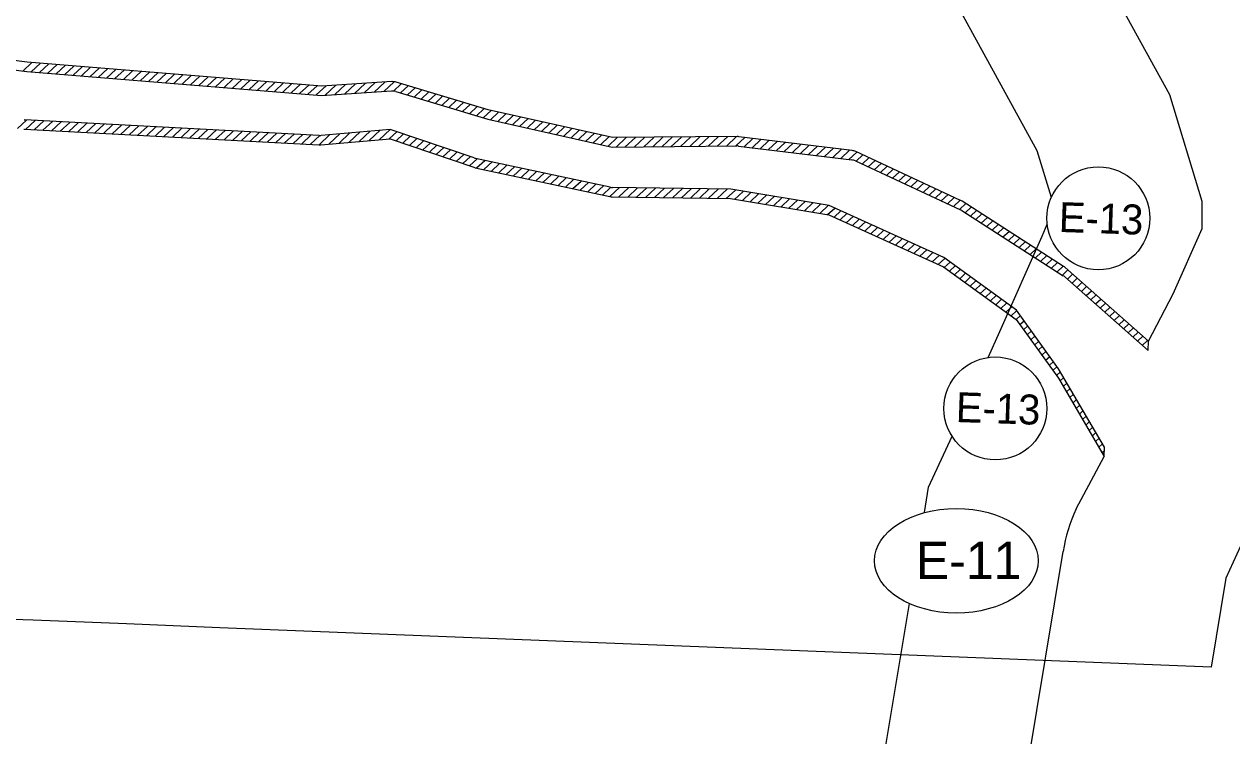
# Model space of a CAD drawing. Extents: x 977239 to 983725, y 1525948 to 1526901.
# Drawn here: x 977835.8 to 978029.8, y 1526495.3 to 1526609.6 of the extents above; entities that cross this region are included whole.
import ezdxf

# ---------------------------------------------------------------- set-up
doc = ezdxf.new("R2010")
doc.units = 0
for name, color, linetype in [('R_Erosion', 7, 'Continuous'), ('R_No Plot', 7, 'Continuous'), ('R_Water', 7, 'Continuous')]:
    doc.layers.add(name, color=color, linetype=linetype)

msp = doc.modelspace()

# ---------------------------------------------------------------- linework, layer by layer
at = {"layer": 'R_Erosion'}
for p, q in [((977835.63, 1526602.04), (977837.08, 1526603.4)), ((977836.95, 1526601.91), (977838.43, 1526603.29)), ((977838.3, 1526601.8), (977839.78, 1526603.18)), ((977839.65, 1526601.69), (977841.13, 1526603.07)), ((977840.99, 1526601.58), (977842.47, 1526602.96)), ((977842.34, 1526601.47), (977843.82, 1526602.85)), ((977843.69, 1526601.36), (977845.17, 1526602.74)), ((977845.04, 1526601.25), (977846.51, 1526602.64)), ((977846.38, 1526601.14), (977847.86, 1526602.53)), ((977847.73, 1526601.03), (977849.21, 1526602.42)), ((977849.08, 1526600.92), (977850.56, 1526602.31)), ((977850.42, 1526600.82), (977851.9, 1526602.2)), ((977851.77, 1526600.71), (977853.25, 1526602.09)), ((977853.12, 1526600.6), (977854.6, 1526601.98)), ((977854.47, 1526600.49), (977855.95, 1526601.87)), ((977855.81, 1526600.38), (977857.29, 1526601.76)), ((977857.16, 1526600.27), (977858.64, 1526601.65)), ((977858.51, 1526600.16), (977859.99, 1526601.55)), ((977859.86, 1526600.05), (977861.33, 1526601.44)), ((977861.2, 1526599.94), (977862.68, 1526601.33)), ((977862.55, 1526599.84), (977864.03, 1526601.22)), ((977863.9, 1526599.73), (977865.38, 1526601.11)), ((977865.25, 1526599.62), (977866.72, 1526601)), ((977866.59, 1526599.51), (977868.07, 1526600.89)), ((977867.94, 1526599.4), (977869.42, 1526600.78)), ((977869.29, 1526599.29), (977870.77, 1526600.67)), ((977870.63, 1526599.18), (977872.11, 1526600.56)), ((977871.98, 1526599.07), (977873.46, 1526600.46)), ((977873.33, 1526598.96), (977874.81, 1526600.35)), ((977874.68, 1526598.85), (977876.16, 1526600.24)), ((977876.02, 1526598.75), (977877.5, 1526600.13)), ((977877.37, 1526598.64), (977878.85, 1526600.02)), ((977878.72, 1526598.53), (977880.2, 1526599.91)), ((977880.07, 1526598.42), (977881.54, 1526599.8)), ((977881.41, 1526598.31), (977882.89, 1526599.69)), ((977882.76, 1526598.2), (977884.33, 1526599.67)), ((977884.19, 1526598.17), (977885.9, 1526599.77)), ((977885.76, 1526598.27), (977887.47, 1526599.87)), ((977887.33, 1526598.36), (977889.04, 1526599.97)), ((977888.9, 1526598.46), (977890.61, 1526600.07)), ((977890.47, 1526598.56), (977892.18, 1526600.17)), ((977892.04, 1526598.66), (977893.75, 1526600.26)), ((977893.6, 1526598.76), (977895.27, 1526600.32)), ((977895.14, 1526598.83), (977896.4, 1526600.01)), ((977896.28, 1526598.53), (977897.51, 1526599.67)), ((977897.39, 1526598.2), (977898.62, 1526599.34)), ((977898.5, 1526597.86), (977899.73, 1526599.01)), ((977899.61, 1526597.53), (977900.83, 1526598.68)), ((977900.72, 1526597.2), (977901.94, 1526598.34)), ((977901.83, 1526596.86), (977903.05, 1526598.01)), ((977902.93, 1526596.53), (977904.16, 1526597.68)), ((977904.04, 1526596.2), (977905.27, 1526597.35)), ((977905.15, 1526595.87), (977906.38, 1526597.01)), ((977906.26, 1526595.53), (977907.48, 1526596.68)), ((977907.37, 1526595.2), (977908.59, 1526596.35)), ((977908.47, 1526594.87), (977909.7, 1526596.01)), ((977909.58, 1526594.54), (977910.84, 1526595.71)), ((977910.72, 1526594.23), (977912.02, 1526595.45)), ((977911.9, 1526593.96), (977913.2, 1526595.18)), ((977834.74, 1526592.8), (977836.21, 1526594.17)), ((977883.24, 1526591.72), (977835.93, 1526594.19)), ((977883.24, 1526591.72), (977835.93, 1526594.19)), ((977883.24, 1526591.72), (977835.93, 1526594.19)), ((977836.07, 1526592.68), (977837.59, 1526594.1)), ((977837.46, 1526592.61), (977838.98, 1526594.03)), ((977838.85, 1526592.53), (977840.37, 1526593.96)), ((977840.23, 1526592.46), (977841.75, 1526593.88)), ((977841.62, 1526592.39), (977843.14, 1526593.81)), ((977843.01, 1526592.32), (977844.53, 1526593.74)), ((977844.39, 1526592.24), (977845.91, 1526593.67)), ((977845.78, 1526592.17), (977847.3, 1526593.59)), ((977847.16, 1526592.1), (977848.69, 1526593.52)), ((977848.55, 1526592.03), (977850.07, 1526593.45)), ((977849.94, 1526591.95), (977851.46, 1526593.38)), ((977851.32, 1526591.88), (977852.84, 1526593.3)), ((977852.71, 1526591.81), (977854.23, 1526593.23)), ((977854.1, 1526591.74), (977855.62, 1526593.16)), ((977913.08, 1526593.7), (977914.38, 1526594.92)), ((977914.26, 1526593.43), (977915.56, 1526594.65)), ((977915.44, 1526593.17), (977916.74, 1526594.39)), ((977916.62, 1526592.9), (977917.93, 1526594.12)), ((977917.8, 1526592.64), (977919.11, 1526593.86)), ((977918.99, 1526592.38), (977920.29, 1526593.6)), ((977920.17, 1526592.11), (977921.47, 1526593.33)), ((977835.88, 1526592.69), (977883.19, 1526590.22)), ((977835.88, 1526592.69), (977883.19, 1526590.22)), ((977855.48, 1526591.66), (977857, 1526593.09)), ((977856.87, 1526591.59), (977858.39, 1526593.01)), ((977858.26, 1526591.52), (977859.78, 1526592.94)), ((977859.64, 1526591.45), (977861.16, 1526592.87)), ((977861.03, 1526591.37), (977862.55, 1526592.8)), ((977862.42, 1526591.3), (977863.94, 1526592.72)), ((977863.8, 1526591.23), (977865.32, 1526592.65)), ((977865.19, 1526591.16), (977866.71, 1526592.58)), ((977866.57, 1526591.09), (977868.1, 1526592.51)), ((977867.96, 1526591.01), (977869.48, 1526592.44)), ((977869.35, 1526590.94), (977870.87, 1526592.36)), ((977870.73, 1526590.87), (977872.25, 1526592.29)), ((977872.12, 1526590.8), (977873.64, 1526592.22)), ((977873.51, 1526590.72), (977875.03, 1526592.15)), ((977874.89, 1526590.65), (977876.41, 1526592.07)), ((977876.28, 1526590.58), (977877.8, 1526592)), ((977877.67, 1526590.51), (977879.19, 1526591.93)), ((977879.05, 1526590.43), (977880.57, 1526591.86)), ((977880.44, 1526590.36), (977881.96, 1526591.78)), ((977881.83, 1526590.29), (977883.35, 1526591.71)), ((977883.21, 1526590.22), (977884.95, 1526591.84)), ((977884.8, 1526590.34), (977886.56, 1526591.98)), ((977886.41, 1526590.47), (977888.17, 1526592.12)), ((977888.03, 1526590.61), (977889.78, 1526592.26)), ((977889.64, 1526590.75), (977891.4, 1526592.39)), ((977891.25, 1526590.89), (977893.01, 1526592.53)), ((977892.86, 1526591.02), (977894.62, 1526592.67)), ((977894.47, 1526591.16), (977895.7, 1526592.31)), ((977895.59, 1526590.84), (977896.77, 1526591.95)), ((977896.66, 1526590.47), (977897.85, 1526591.58)), ((977897.73, 1526590.11), (977898.92, 1526591.22)), ((977921.35, 1526591.85), (977922.65, 1526593.07)), ((977922.53, 1526591.58), (977923.83, 1526592.8)), ((977923.71, 1526591.32), (977925.01, 1526592.54)), ((977924.89, 1526591.05), (977926.19, 1526592.27)), ((977926.07, 1526590.79), (977927.38, 1526592.01)), ((977927.25, 1526590.53), (977928.56, 1526591.75)), ((977928.44, 1526590.26), (977929.74, 1526591.48)), ((977929.62, 1526590), (977931.07, 1526591.35)), ((977930.93, 1526589.85), (977932.54, 1526591.37)), ((977932.4, 1526589.87), (977934.02, 1526591.38)), ((977933.88, 1526589.88), (977935.5, 1526591.39)), ((977935.36, 1526589.89), (977936.98, 1526591.4)), ((977936.84, 1526589.9), (977938.45, 1526591.42)), ((977938.31, 1526589.92), (977939.93, 1526591.43)), ((977939.79, 1526589.93), (977941.41, 1526591.44)), ((977941.27, 1526589.94), (977942.88, 1526591.45)), ((977942.74, 1526589.95), (977944.36, 1526591.47)), ((977944.22, 1526589.97), (977945.84, 1526591.48)), ((977945.7, 1526589.98), (977947.32, 1526591.49)), ((977947.18, 1526589.99), (977948.79, 1526591.5)), ((977948.65, 1526590), (977950.27, 1526591.52)), ((977950.13, 1526590.02), (977951.59, 1526591.39)), ((977968.82, 1526589.29), (977950.64, 1526591.5)), ((977968.82, 1526589.29), (977950.64, 1526591.5)), ((977951.47, 1526589.9), (977952.89, 1526591.23)), ((977898.81, 1526589.74), (977899.99, 1526590.85)), ((977899.88, 1526589.38), (977901.07, 1526590.49)), ((977900.95, 1526589.01), (977902.14, 1526590.12)), ((977902.03, 1526588.65), (977903.22, 1526589.76)), ((977903.1, 1526588.28), (977904.29, 1526589.39)), ((977950.59, 1526590), (977968.77, 1526587.79)), ((977952.76, 1526589.74), (977954.18, 1526591.07)), ((977954.06, 1526589.58), (977955.48, 1526590.91)), ((977955.35, 1526589.42), (977956.77, 1526590.75)), ((977956.65, 1526589.26), (977958.07, 1526590.6)), ((977957.94, 1526589.11), (977959.36, 1526590.44)), ((977959.24, 1526588.95), (977960.66, 1526590.28)), ((977960.53, 1526588.79), (977961.95, 1526590.12)), ((977961.83, 1526588.63), (977963.25, 1526589.96)), ((977963.12, 1526588.48), (977964.54, 1526589.81)), ((977964.42, 1526588.32), (977965.84, 1526589.65)), ((977965.71, 1526588.16), (977967.13, 1526589.49)), ((977967.01, 1526588), (977968.43, 1526589.33)), ((977904.17, 1526587.92), (977905.36, 1526589.03)), ((977905.25, 1526587.55), (977906.44, 1526588.66)), ((977906.32, 1526587.19), (977907.51, 1526588.3)), ((977907.39, 1526586.82), (977908.62, 1526587.97)), ((977929.96, 1526583.39), (977908.34, 1526588.03)), ((977929.96, 1526583.39), (977908.34, 1526588.03)), ((977929.96, 1526583.39), (977908.34, 1526588.03)), ((977908.5, 1526586.49), (977909.81, 1526587.71)), ((977909.69, 1526586.23), (977911, 1526587.46)), ((977968.3, 1526587.84), (977969.58, 1526589.04)), ((977969.37, 1526587.61), (977986.22, 1526579.77)), ((977986.27, 1526581.27), (977969.42, 1526589.11)), ((977986.27, 1526581.27), (977969.42, 1526589.11)), ((977969.47, 1526587.57), (977970.56, 1526588.59)), ((977970.45, 1526587.11), (977971.53, 1526588.13)), ((977971.43, 1526586.66), (977972.51, 1526587.68)), ((977908.29, 1526586.53), (977929.91, 1526581.89)), ((977908.29, 1526586.53), (977929.91, 1526581.89)), ((977910.88, 1526585.98), (977912.19, 1526587.2)), ((977912.07, 1526585.72), (977913.39, 1526586.95)), ((977913.26, 1526585.46), (977914.58, 1526586.69)), ((977914.45, 1526585.21), (977915.77, 1526586.44)), ((977915.65, 1526584.95), (977916.96, 1526586.18)), ((977916.84, 1526584.7), (977918.15, 1526585.93)), ((977918.03, 1526584.44), (977919.34, 1526585.67)), ((977919.22, 1526584.19), (977920.53, 1526585.42)), ((977972.4, 1526586.2), (977973.49, 1526587.22)), ((977973.38, 1526585.75), (977974.47, 1526586.77)), ((977974.36, 1526585.29), (977975.44, 1526586.31)), ((977975.33, 1526584.84), (977976.42, 1526585.85)), ((977976.31, 1526584.38), (977977.4, 1526585.4)), ((977920.41, 1526583.93), (977921.72, 1526585.16)), ((977921.6, 1526583.68), (977922.91, 1526584.91)), ((977922.79, 1526583.42), (977924.1, 1526584.65)), ((977923.98, 1526583.17), (977925.29, 1526584.39)), ((977925.17, 1526582.91), (977926.48, 1526584.14)), ((977926.36, 1526582.66), (977927.68, 1526583.88)), ((977927.55, 1526582.4), (977928.87, 1526583.63)), ((977977.29, 1526583.93), (977978.38, 1526584.94)), ((977978.27, 1526583.47), (977979.35, 1526584.49)), ((977979.24, 1526583.02), (977980.33, 1526584.03)), ((977980.22, 1526582.56), (977981.31, 1526583.58)), ((977928.74, 1526582.14), (977930.06, 1526583.38)), ((977929.93, 1526581.89), (977931.48, 1526583.33)), ((977931.34, 1526581.83), (977932.92, 1526583.31)), ((977932.78, 1526581.81), (977934.36, 1526583.29)), ((977934.22, 1526581.79), (977935.8, 1526583.27)), ((977935.66, 1526581.77), (977937.24, 1526583.24)), ((977937.1, 1526581.75), (977938.68, 1526583.22)), ((977938.54, 1526581.72), (977940.12, 1526583.2)), ((977939.98, 1526581.7), (977941.56, 1526583.18)), ((977941.42, 1526581.68), (977943, 1526583.16)), ((977942.86, 1526581.66), (977944.44, 1526583.14)), ((977944.3, 1526581.64), (977945.88, 1526583.11)), ((977945.74, 1526581.62), (977947.32, 1526583.09)), ((977947.18, 1526581.59), (977948.76, 1526583.07)), ((977948.62, 1526581.57), (977950.09, 1526582.94)), ((977949.96, 1526581.45), (977951.33, 1526582.73)), ((977951.21, 1526581.25), (977952.58, 1526582.53)), ((977952.45, 1526581.04), (977953.82, 1526582.33)), ((977953.7, 1526580.84), (977955.07, 1526582.12)), ((977954.94, 1526580.63), (977956.31, 1526581.92)), ((977956.19, 1526580.43), (977957.56, 1526581.71)), ((977957.43, 1526580.23), (977958.8, 1526581.51)), ((977981.2, 1526582.11), (977982.29, 1526583.12)), ((977982.18, 1526581.65), (977983.26, 1526582.67)), ((977983.15, 1526581.2), (977984.24, 1526582.21)), ((977984.13, 1526580.74), (977985.22, 1526581.76)), ((977958.68, 1526580.02), (977960.05, 1526581.3)), ((977959.92, 1526579.82), (977961.29, 1526581.1)), ((977961.17, 1526579.61), (977962.54, 1526580.89)), ((977962.41, 1526579.41), (977963.78, 1526580.69)), ((977963.66, 1526579.2), (977965.03, 1526580.49)), ((977964.9, 1526579), (977966.04, 1526580.06)), ((977965.93, 1526578.59), (977967.02, 1526579.61)), ((977985.11, 1526580.29), (977986.19, 1526581.3)), ((977986.09, 1526579.83), (977987.09, 1526580.77)), ((977986.46, 1526579.64), (978002.76, 1526569.19)), ((978002.81, 1526570.69), (977986.51, 1526581.14)), ((978002.81, 1526570.69), (977986.51, 1526581.14)), ((977986.98, 1526579.3), (977987.95, 1526580.21)), ((977987.85, 1526578.75), (977988.82, 1526579.65)), ((977966.91, 1526578.14), (977968.01, 1526579.16)), ((977967.9, 1526577.69), (977968.99, 1526578.71)), ((977968.88, 1526577.24), (977969.98, 1526578.27)), ((977969.87, 1526576.8), (977970.96, 1526577.82)), ((977988.72, 1526578.19), (977989.69, 1526579.1)), ((977989.59, 1526577.63), (977990.56, 1526578.54)), ((977990.46, 1526577.08), (977991.43, 1526577.98)), ((977970.85, 1526576.35), (977971.95, 1526577.37)), ((977971.84, 1526575.9), (977972.93, 1526576.92)), ((977972.82, 1526575.45), (977973.92, 1526576.48)), ((977973.81, 1526575), (977974.9, 1526576.03)), ((977991.33, 1526576.52), (977992.3, 1526577.43)), ((977992.2, 1526575.96), (977993.17, 1526576.87)), ((977993.06, 1526575.41), (977994.04, 1526576.31)), ((977993.93, 1526574.85), (977994.9, 1526575.76)), ((977974.79, 1526574.56), (977975.89, 1526575.58)), ((977975.78, 1526574.11), (977976.87, 1526575.13)), ((977976.76, 1526573.66), (977977.86, 1526574.69)), ((977977.75, 1526573.21), (977978.85, 1526574.24)), ((977978.74, 1526572.77), (977979.83, 1526573.79)), ((977994.8, 1526574.29), (977995.77, 1526575.2)), ((977995.67, 1526573.74), (977996.64, 1526574.64)), ((977996.54, 1526573.18), (977997.51, 1526574.09)), ((977979.72, 1526572.32), (977980.82, 1526573.34)), ((977980.71, 1526571.87), (977981.8, 1526572.9)), ((977981.69, 1526571.42), (977982.79, 1526572.45)), ((977982.68, 1526570.98), (977983.73, 1526571.97)), ((977997.41, 1526572.62), (977998.38, 1526573.53)), ((977998.28, 1526572.07), (977999.25, 1526572.97)), ((977999.14, 1526571.51), (978000.12, 1526572.42)), ((978000.01, 1526570.95), (978000.99, 1526571.86)), ((977983.63, 1526570.5), (977984.56, 1526571.37)), ((977984.46, 1526569.91), (977985.39, 1526570.77)), ((977985.29, 1526569.31), (977986.21, 1526570.18)), ((978000.88, 1526570.4), (978001.85, 1526571.3)), ((978001.75, 1526569.84), (978002.72, 1526570.75)), ((978002.62, 1526569.28), (978003.5, 1526570.11)), ((978016.43, 1526558.68), (978003.05, 1526570.51)), ((978016.43, 1526558.68), (978003.05, 1526570.51)), ((977986.11, 1526568.71), (977987.04, 1526569.58)), ((977986.94, 1526568.12), (977987.87, 1526568.99)), ((977987.77, 1526567.52), (977988.69, 1526568.39)), ((978003, 1526569.01), (978016.38, 1526557.18)), ((978003.41, 1526568.65), (978004.26, 1526569.44)), ((978004.16, 1526567.99), (978005.01, 1526568.78)), ((978004.91, 1526567.32), (978005.76, 1526568.11)), ((977988.59, 1526566.93), (977989.52, 1526567.79)), ((977989.42, 1526566.33), (977990.35, 1526567.2)), ((977990.25, 1526565.73), (977991.17, 1526566.6)), ((977991.07, 1526565.14), (977992, 1526566.01)), ((978005.67, 1526566.65), (978006.51, 1526567.45)), ((978006.42, 1526565.99), (978007.27, 1526566.78)), ((978007.17, 1526565.32), (978008.02, 1526566.12)), ((978016.43, 1526558.68), (978020.39, 1526566.26)), ((977991.9, 1526564.54), (977992.83, 1526565.41)), ((977992.73, 1526563.95), (977993.65, 1526564.81)), ((977993.55, 1526563.35), (977994.48, 1526564.22)), ((978007.92, 1526564.66), (978008.77, 1526565.45)), ((978008.68, 1526563.99), (978009.53, 1526564.79)), ((978009.43, 1526563.33), (978010.28, 1526564.12)), ((977994.38, 1526562.75), (977995.29, 1526563.61)), ((977995.21, 1526562.16), (977995.88, 1526562.79)), ((978010.18, 1526562.66), (978011.03, 1526563.46)), ((978010.93, 1526562), (978011.78, 1526562.79)), ((978011.69, 1526561.33), (978012.54, 1526562.13)), ((977995.8, 1526561.34), (977996.47, 1526561.97)), ((977996.38, 1526560.52), (977997.06, 1526561.15)), ((977996.97, 1526559.7), (977997.65, 1526560.33)), ((978012.44, 1526560.67), (978013.29, 1526561.46)), ((978013.19, 1526560), (978014.04, 1526560.8)), ((977997.56, 1526558.88), (977998.24, 1526559.52)), ((977998.15, 1526558.07), (977998.83, 1526558.7)), ((978013.95, 1526559.34), (978014.79, 1526560.13)), ((978014.7, 1526558.67), (978015.55, 1526559.47)), ((978015.45, 1526558.01), (978016.3, 1526558.8)), ((978016.38, 1526557.18), (978016.43, 1526558.68)), ((977998.74, 1526557.25), (977999.41, 1526557.88)), ((977999.33, 1526556.43), (978000, 1526557.06)), ((978016.2, 1526557.34), (978016.39, 1526557.52)), ((977999.92, 1526555.61), (978000.59, 1526556.24)), ((978000.51, 1526554.79), (978001.18, 1526555.42)), ((978001.1, 1526553.97), (978001.77, 1526554.6)), ((978001.68, 1526553.15), (978002.32, 1526553.75)), ((978002.24, 1526552.3), (978002.83, 1526552.86)), ((978002.75, 1526551.41), (978003.35, 1526551.97)), ((978003.27, 1526550.53), (978003.87, 1526551.09)), ((978003.79, 1526549.64), (978004.38, 1526550.2)), ((978004.3, 1526548.76), (978004.9, 1526549.32)), ((978004.82, 1526547.87), (978005.42, 1526548.43)), ((978005.34, 1526546.98), (978005.93, 1526547.54)), ((978005.85, 1526546.1), (978006.45, 1526546.66)), ((978006.37, 1526545.21), (978006.97, 1526545.77)), ((978006.89, 1526544.33), (978007.48, 1526544.89)), ((978007.4, 1526543.44), (978008, 1526544)), ((978007.92, 1526542.56), (978008.52, 1526543.12)), ((978008.44, 1526541.67), (978009.03, 1526542.23)), ((978008.95, 1526540.78), (978009.35, 1526541.15)), ((978009.32, 1526540.16), (978009.37, 1526541.66)), ((978009.32, 1526540.16), (978009.37, 1526541.66)), ((978004.82, 1526531.75), (978009.32, 1526540.16)), ((977995.22, 1526479.66), (978002.72, 1526524.9))]:
    msp.add_line(p, q, dxfattribs=at)
for points in [[(978020.39, 1526566.26), (978025.04, 1526576.78), (978025.06, 1526581.12), (978019.89, 1526598.22), (978005.48, 1526624.4)], [(977894.88, 1526600.34), (977883.67, 1526599.63), (977836.29, 1526603.46), (977821.08, 1526605.42)], [(977894.88, 1526600.34), (977883.67, 1526599.63), (977836.29, 1526603.46), (977821.08, 1526605.42)], [(977821.03, 1526603.92), (977836.24, 1526601.96), (977883.62, 1526598.13), (977894.83, 1526598.84)], [(977950.38, 1526591.52), (977930.33, 1526591.35), (977910.36, 1526595.82), (977895.58, 1526600.25)], [(977950.38, 1526591.52), (977930.33, 1526591.35), (977910.36, 1526595.82), (977895.58, 1526600.25)], [(977895.53, 1526598.76), (977910.31, 1526594.32), (977930.28, 1526589.85), (977950.33, 1526590.02)], [(977908.11, 1526588.09), (977894.65, 1526592.67), (977883.52, 1526591.72)], [(977908.11, 1526588.09), (977894.65, 1526592.67), (977883.52, 1526591.72)], [(977908.11, 1526588.09), (977894.65, 1526592.67), (977883.52, 1526591.72)], [(977883.47, 1526590.22), (977894.6, 1526591.17), (977908.06, 1526586.59)], [(977883.47, 1526590.22), (977894.6, 1526591.17), (977908.06, 1526586.59)], [(977930.3, 1526581.85), (977949.3, 1526581.56), (977965.08, 1526578.97), (977983.49, 1526570.61), (977995.21, 1526562.16), (978001.96, 1526552.77), (978009.32, 1526540.16)], [(977930.3, 1526581.85), (977949.3, 1526581.56), (977965.08, 1526578.97), (977983.49, 1526570.61), (977995.21, 1526562.16), (978001.96, 1526552.77), (978009.32, 1526540.16)], [(978009.37, 1526541.66), (978002.01, 1526554.27), (977995.26, 1526563.66), (977983.54, 1526572.11), (977965.13, 1526580.47), (977949.35, 1526583.06), (977930.35, 1526583.35)], [(978009.37, 1526541.66), (978002.01, 1526554.27), (977995.26, 1526563.66), (977983.54, 1526572.11), (977965.13, 1526580.47), (977949.35, 1526583.06), (977930.35, 1526583.35)], [(978009.37, 1526541.66), (978002.01, 1526554.27), (977995.26, 1526563.66), (977983.54, 1526572.11), (977965.13, 1526580.47), (977949.35, 1526583.06), (977930.35, 1526583.35)]]:
    msp.add_lwpolyline(points, dxfattribs=at)
for centre in [(978008.39, 1526578.41), (977991.84, 1526547.89)]:
    msp.add_circle(centre, 8.26, dxfattribs=at)
for centre, radius, start, end in [((977895, 1526598.34), 2, 73.2894, 93.5983), ((977895, 1526598.34), 2, 73.2894, 93.5983), ((977894.95, 1526596.84), 2, 73.2894, 93.5983), ((977836.03, 1526596.19), 2, 264.13, 267.0103), ((977836.03, 1526596.19), 2, 264.13, 267.0103), ((977836.03, 1526596.19), 2, 264.13, 267.0103), ((977835.98, 1526594.69), 2, 264.13, 267.0103), ((977835.98, 1526594.69), 2, 264.13, 267.0103), ((977883.34, 1526593.71), 2, 267.0103, 274.8843), ((977883.34, 1526593.71), 2, 267.0103, 274.8843), ((977883.34, 1526593.71), 2, 267.0103, 274.8843), ((977950.4, 1526589.52), 2, 83.0488, 90.4832), ((977950.4, 1526589.52), 2, 83.0488, 90.4832), ((977883.3, 1526592.21), 2, 267.0103, 274.8843), ((977883.3, 1526592.21), 2, 267.0103, 274.8843), ((977950.35, 1526588.02), 2, 83.0488, 90.4832), ((977968.58, 1526587.3), 2, 65.0304, 83.0488), ((977968.58, 1526587.3), 2, 65.0304, 83.0488), ((977908.76, 1526589.99), 2, 251.216, 257.8955), ((977908.76, 1526589.99), 2, 251.216, 257.8955), ((977908.76, 1526589.99), 2, 251.216, 257.8955), ((977968.53, 1526585.8), 2, 65.0304, 83.0488), ((977908.71, 1526588.49), 2, 251.216, 257.8955), ((977908.71, 1526588.49), 2, 251.216, 257.8955), ((977930.33, 1526583.85), 2, 257.8955, 269.1291), ((977930.33, 1526583.85), 2, 257.8955, 269.1291), ((977930.38, 1526585.35), 2, 257.8955, 269.1291), ((977930.38, 1526585.35), 2, 257.8955, 269.1291), ((977930.38, 1526585.35), 2, 257.8955, 269.1291), ((977985.38, 1526577.96), 2, 57.3491, 65.0304), ((977985.43, 1526579.46), 2, 57.3491, 65.0304), ((977985.43, 1526579.46), 2, 57.3491, 65.0304), ((978001.73, 1526569.01), 2, 48.5255, 57.3491), ((978001.73, 1526569.01), 2, 48.5255, 57.3491), ((978001.68, 1526567.51), 2, 48.5255, 57.3491), ((978045.09, 1526555.35), 27, 156.1633, 156.1663), ((978029.36, 1526520.49), 27, 155.348, 170.5872)]:
    msp.add_arc(centre, radius, start, end, dxfattribs=at)
msp.add_ellipse((977985.58, 1526523.44), major_axis=(13.15, 0), ratio=0.638788, dxfattribs=at)
at = {"layer": 'R_No Plot'}
for points in [[(977962.65, 1526747.84), (977968.99, 1526733.18), (977977.19, 1526717.98), (977985.41, 1526702.75), (977999.41, 1526685.31), (978013.35, 1526667.94), (978028.7, 1526637.19), (978044.45, 1526608.56), (978051.59, 1526584.97), (978051.51, 1526571.11), (978044.63, 1526555.55), (978037.71, 1526539.89), (978028.88, 1526520.64), (978026.51, 1526506.34)], [(978026.51, 1526506.34), (977867.28, 1526512.69), (977852.29, 1526513.32), (977837.3, 1526513.9), (977822.31, 1526514.41)]]:
    msp.add_lwpolyline(points, dxfattribs=at)
for centre in [(978008.39, 1526578.41), (977991.84, 1526547.89)]:
    msp.add_circle(centre, 8.26, dxfattribs=at)
msp.add_ellipse((977985.58, 1526523.44), major_axis=(13.15, 0), ratio=0.638788, dxfattribs=at)
at = {"layer": 'R_Water'}
for points in [[(978000.84, 1526581.76), (977998.58, 1526589.25), (977985.47, 1526613.06)], [(977990.67, 1526556.07), (977992.58, 1526560.22), (977999.35, 1526575.55), (978000.18, 1526577.44)], [(977980.45, 1526531.17), (977981.13, 1526535.26), (977984.88, 1526543.45)], [(977981.3, 1526442.85), (977970.15, 1526469.06), (977978.03, 1526516.57)]]:
    msp.add_lwpolyline(points, dxfattribs=at)

# ---------------------------------------------------------------- texts
at = {"layer": 'R_Erosion'}
for p in [(978001.98, 1526576.22), (977985.44, 1526545.71)]:
    msp.add_text('E-13', height=4.8, rotation=358.0901, dxfattribs=at).set_placement(p)
msp.add_text('E-11', height=5.999, dxfattribs=at).set_placement((977979.09, 1526520.49))

doc.saveas('drawing.dxf')
